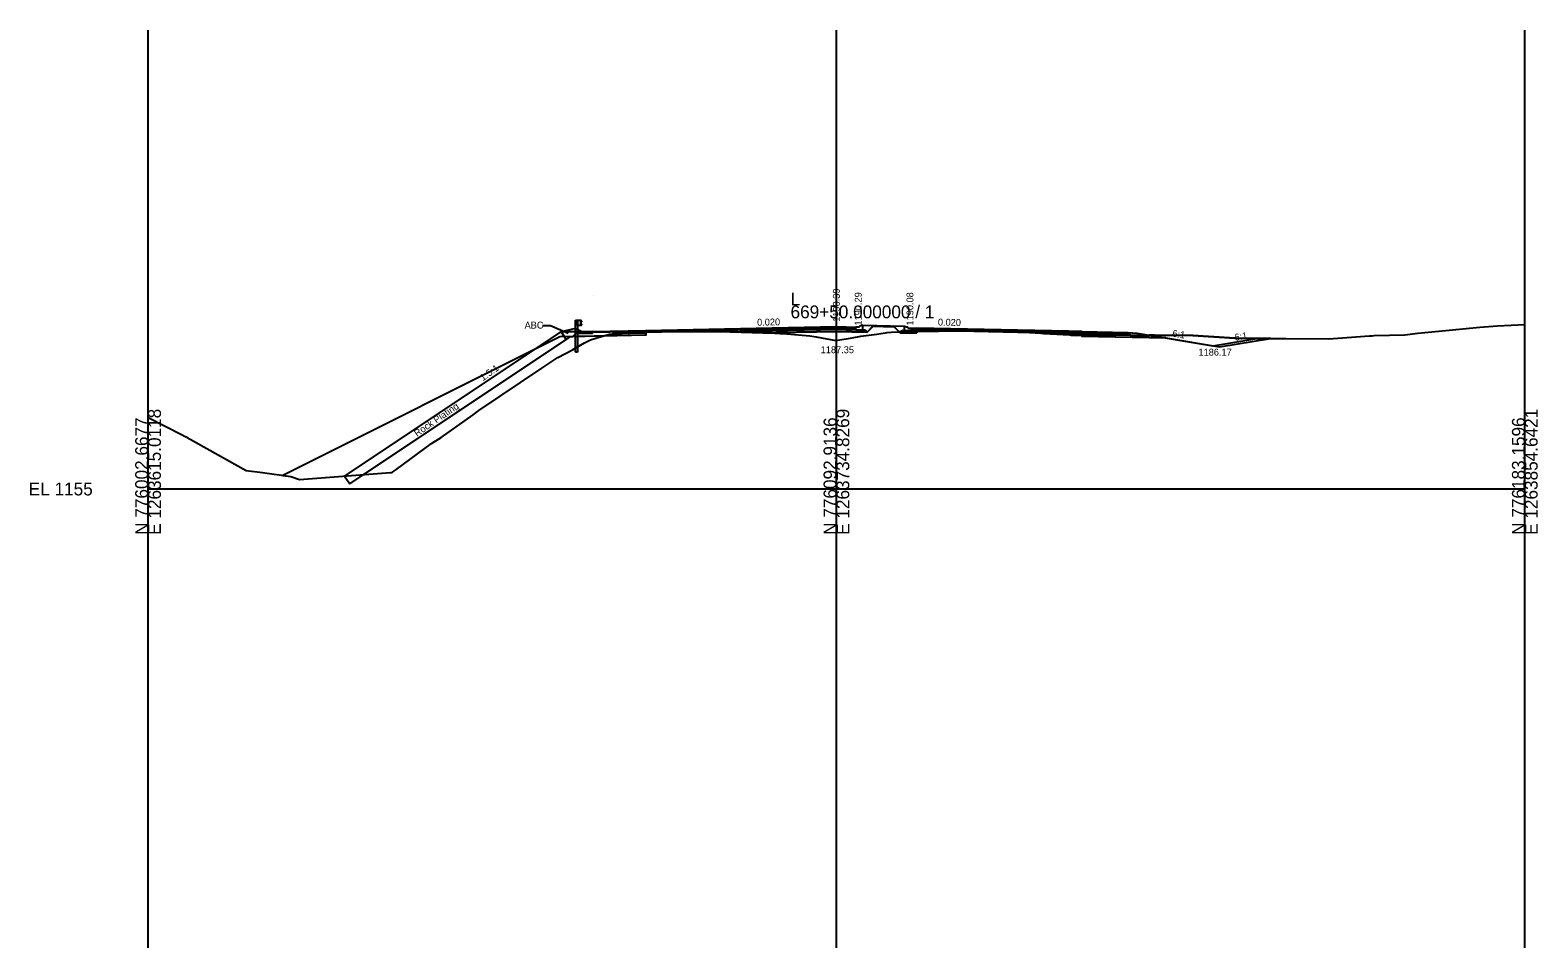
# Model space of a CAD drawing. Extents: x -41 to 1262860, y -100 to 777489.
# Drawn here: x -25.7 to 302.8, y 3130 to 3330 of the extents above; entities that cross this region are included whole.
import ezdxf

# ---------------------------------------------------------------- set-up
doc = ezdxf.new("R2010")
doc.units = 0
for name, color, linetype in [('Exist Cross Section Cell', 7, 'Continuous'), ('Exist XS Center Line Elevation Label', 7, 'Continuous'), ('Exist XS Ground Line', 7, 'Continuous'), ('Prop CMT Guardrail Graphics', 7, 'Continuous'), ('Prop CMT Pvmt Course 1', 7, 'Continuous'), ('Prop CMT Pvmt Course 2', 7, 'Continuous'), ('Prop CMT Pvmt Course 4', 7, 'Continuous'), ('Prop CMT Pvmt Surface', 7, 'Continuous'), ('Prop CMT Shld Paved Course 1', 7, 'Continuous'), ('Prop CMT Shld Paved Course 2', 7, 'Continuous'), ('Prop CMT Shld Paved Course 4', 7, 'Continuous'), ('Prop CMT Slope Grass', 7, 'Continuous'), ('Prop CMT Subgrade Earthwork', 7, 'Continuous'), ('Prop Conc Curb and Gutter', 7, 'Continuous'), ('Prop Conc Island Cover', 7, 'Continuous'), ('Prop XS Class II Rip Rap Ditch Liner', 7, 'Continuous'), ('Prop XS Ditch Standard Text', 7, 'Continuous'), ('Prop XS Earthwork Shape', 7, 'Continuous'), ('Prop XS Elevation Labels', 7, 'Continuous'), ('Prop XS Exc Vertical Line 1', 7, 'Continuous'), ('Prop XS Exc Vertical Line 2', 7, 'Continuous'), ('Prop XS Exc Vertical Line 3', 7, 'Continuous'), ('Prop XS Finish Grade', 7, 'Continuous'), ('Prop XS Hydro Elevations', 7, 'Continuous'), ('Prop XS SE Text', 7, 'Continuous'), ('Prop XS Side Slope Text', 7, 'Continuous'), ('Scratch_Level_0', 7, 'Continuous'), ('Scratch_Level_4', 7, 'Continuous'), ('Scratch_Level_5', 7, 'Continuous'), ('Scratch_Level_6', 7, 'Continuous'), ('Typical Curb CELL', 7, 'Continuous')]:
    doc.layers.add(name, color=color, linetype=linetype)

msp = doc.modelspace()

# ---------------------------------------------------------------- linework, layer by layer
at = {"layer": 'Exist Cross Section Cell'}
for p, q in [((150, 3230), (150, 3270)), ((0, 3230), (150, 3230)), ((150, 3230), (300, 3230))]:
    msp.add_line(p, q, dxfattribs=at)
at = {"layer": 'Exist XS Ground Line'}
msp.add_lwpolyline([(0, 3245.57), (7.42, 3241.82), (7.97, 3241.54), (8.29, 3241.35), (8.55, 3241.2), (21.4, 3234.01), (24.93, 3233.6), (31.13, 3232.71), (32.97, 3232.08), (52.85, 3233.58), (52.95, 3233.57), (53.09, 3233.61), (53.19, 3233.61), (53.34, 3233.71), (53.98, 3234.17), (61.78, 3239.91), (63.88, 3241.26), (70.84, 3246.15), (72.07, 3247.09), (85.84, 3256.37), (89.26, 3258.65), (92.52, 3260.3), (95.1, 3261.85), (96.38, 3262.52), (98.28, 3263.08), (100.55, 3263.76), (106.09, 3264.06), (107.94, 3264.15), (108.32, 3264.17), (111.86, 3264.28), (124.04, 3264.35), (124.13, 3264.35), (124.32, 3264.35), (136.54, 3263.94), (137.74, 3263.89), (139.19, 3263.82), (144.17, 3263.38), (145.58, 3263.17), (149.9, 3262.33), (153.44, 3262.98), (155.3, 3263.29), (158.77, 3263.76), (161.02, 3264.13), (161.89, 3264.17), (164.81, 3264.31), (167.6, 3264.34), (176.86, 3264.46), (179.93, 3264.39), (189.56, 3264.21), (192.06, 3264.08), (200.8, 3263.59), (201.1, 3263.56), (202.37, 3263.44), (203.52, 3263.49), (205.24, 3263.58), (214.29, 3263.54), (219.34, 3263.51), (227.67, 3263.44), (236.79, 3262.85), (240.26, 3262.81), (245.15, 3262.81), (246.28, 3262.83), (247.9, 3262.83), (257.29, 3262.72), (266.14, 3263.35), (266.72, 3263.39), (267.17, 3263.42), (273.85, 3263.61), (276.69, 3263.95), (281.26, 3264.41), (290.22, 3265.3), (294.07, 3265.58), (300, 3265.86)], dxfattribs=at)
at = {"layer": 'Prop CMT Guardrail Graphics'}
for p, q in [((93.11, 3266.79), (93.59, 3266.79)), ((93.11, 3264.29), (93.11, 3266.79)), ((93.59, 3265.61), (93.59, 3266.79)), ((93.59, 3266.79), (94.26, 3266.79)), ((93.59, 3266.79), (93.59, 3264.28)), ((94.26, 3266.79), (94.26, 3265.61)), ((94.26, 3266.71), (94.26, 3265.69)), ((94.36, 3266.69), (94.26, 3266.71)), ((94.26, 3265.69), (94.36, 3265.71)), ((94.27, 3266.24), (94.5, 3266.44)), ((94.27, 3266.15), (94.27, 3266.24)), ((94.5, 3265.95), (94.27, 3266.15)), ((94.5, 3266.59), (94.36, 3266.69)), ((94.36, 3265.71), (94.5, 3265.81)), ((94.5, 3266.44), (94.5, 3266.59)), ((94.5, 3265.81), (94.5, 3265.95)), ((93.11, 3259.79), (93.11, 3264.29)), ((94.26, 3265.61), (93.59, 3265.61)), ((93.59, 3264.28), (93.59, 3259.79)), ((93.59, 3259.79), (93.11, 3259.79))]:
    msp.add_line(p, q, dxfattribs=at)
at = {"layer": 'Prop CMT Pvmt Course 1'}
for p, q in [((94.5, 3264.28), (108.5, 3264.56)), ((132.5, 3265.04), (150, 3265.39)), ((132.5, 3264.79), (150, 3265.14)), ((150, 3265.39), (154.23, 3265.3)), ((150, 3265.14), (154.23, 3265.05)), ((154.23, 3265.3), (154.23, 3265.05)), ((166.33, 3265.06), (166.33, 3264.81)), ((166.33, 3265.06), (167.5, 3265.04)), ((203.5, 3264.32), (213.5, 3264.12))]:
    msp.add_line(p, q, dxfattribs=at)
for points in [[(108.5, 3264.31), (108.5, 3264.56), (108.5, 3264.56), (132.5, 3265.04), (132.5, 3264.79), (132.5, 3264.79), (108.5, 3264.31), (108.5, 3264.31), (108.5, 3264.31)], [(203.5, 3264.07), (203.5, 3264.32), (200.57, 3264.38), (200.57, 3264.38), (200.57, 3264.38), (167.5, 3265.04), (167.5, 3264.79), (167.5, 3264.79), (200.57, 3264.13), (200.57, 3264.13), (200.57, 3264.13), (203.5, 3264.07), (203.5, 3264.07)]]:
    msp.add_lwpolyline(points, dxfattribs=at)
at = {"layer": 'Prop CMT Pvmt Course 2'}
msp.add_lwpolyline([(166.33, 3264.48), (167.5, 3264.46), (167.5, 3264.46), (167.5, 3264.79), (166.33, 3264.81)], dxfattribs=at)
at = {"layer": 'Prop CMT Pvmt Course 4'}
for p, q in [((108.5, 3263.52), (93.44, 3263.22)), ((132.5, 3264.46), (132.5, 3264)), ((132.5, 3264), (150, 3264.35)), ((132.5, 3264), (150, 3264.35)), ((150, 3264.35), (156.69, 3264.21)), ((163.88, 3264.07), (167.5, 3264)), ((166.33, 3264.02), (166.33, 3264.48)), ((167.5, 3264.46), (167.5, 3264))]:
    msp.add_line(p, q, dxfattribs=at)
at = {"layer": 'Prop CMT Pvmt Surface'}
for p, q in [((96.85, 3264.33), (108.5, 3264.56)), ((108.5, 3264.56), (132.5, 3265.04)), ((132.5, 3265.04), (150, 3265.39)), ((150, 3265.39), (154.23, 3265.3)), ((166.33, 3265.06), (167.5, 3265.04)), ((167.5, 3265.04), (203.5, 3264.32)), ((203.5, 3264.32), (213.5, 3264.12))]:
    msp.add_line(p, q, dxfattribs=at)
at = {"layer": 'Prop CMT Shld Paved Course 1'}
for p, q in [((108.5, 3264.31), (96.85, 3264.08)), ((104.5, 3264.48), (104.5, 3264.48)), ((108.5, 3264.56), (108.5, 3264.31)), ((108.5, 3264.31), (108.5, 3264.31)), ((203.5, 3264.32), (203.5, 3264.07)), ((203.5, 3264.07), (203.5, 3264.07)), ((203.5, 3264.07), (213.76, 3263.86)), ((207.5, 3264.24), (207.5, 3264.24)), ((213.76, 3263.86), (213.5, 3264.12))]:
    msp.add_line(p, q, dxfattribs=at)
at = {"layer": 'Prop CMT Shld Paved Course 2'}
for p, q in [((97.1, 3272.23), (97.1, 3272.23)), ((97.1, 3272.23), (97.1, 3272.23)), ((97.1, 3272.23), (97.1, 3272.23)), ((97.1, 3272.23), (97.1, 3272.23)), ((97.1, 3272.23), (97.1, 3272.23)), ((97.1, 3272.23), (97.1, 3272.23)), ((108.5, 3263.98), (101.18, 3263.83)), ((103.9, 3263.88), (103.9, 3263.88)), ((103.9, 3263.88), (103.9, 3263.88)), ((111.86, 3264.38), (108.5, 3264.31)), ((108.5, 3264.31), (108.5, 3263.98)), ((108.5, 3264.31), (108.5, 3264.31)), ((108.5, 3264.31), (108.5, 3264.17)), ((108.5, 3264.17), (111.86, 3264.28)), ((108.5, 3264.17), (108.5, 3264.17)), ((108.5, 3264.17), (108.5, 3264.17)), ((108.5, 3263.98), (108.5, 3263.98)), ((124.04, 3264.62), (111.86, 3264.38)), ((111.86, 3264.38), (111.86, 3264.38)), ((111.86, 3264.38), (111.86, 3264.38)), ((111.86, 3264.28), (124.04, 3264.35)), ((111.86, 3264.28), (111.86, 3264.28)), ((111.86, 3264.28), (111.86, 3264.28)), ((124.13, 3264.62), (124.04, 3264.62)), ((124.04, 3264.62), (124.04, 3264.62)), ((124.04, 3264.35), (124.04, 3264.35)), ((124.04, 3264.35), (124.13, 3264.35)), ((124.32, 3264.63), (124.13, 3264.62)), ((124.13, 3264.35), (124.32, 3264.35)), ((132.5, 3264.79), (124.32, 3264.63)), ((124.32, 3264.63), (124.32, 3264.63)), ((124.32, 3264.35), (124.32, 3264.35)), ((124.32, 3264.35), (125.36, 3264.31)), ((125.36, 3264.31), (132.5, 3264.46)), ((125.36, 3264.31), (125.36, 3264.31)), ((132.5, 3264.46), (150, 3264.81)), ((132.5, 3264.46), (132.5, 3264.79)), ((132.5, 3264.79), (132.5, 3264.79)), ((132.5, 3264.46), (132.5, 3264.46)), ((132.5, 3264.46), (132.5, 3264.46)), ((150, 3264.81), (154.23, 3264.72)), ((154.23, 3264.72), (154.23, 3265.05)), ((166.33, 3264.48), (166.33, 3264.81)), ((203.5, 3264.07), (203.5, 3263.74)), ((203.5, 3263.74), (203.5, 3263.74)), ((203.5, 3263.74), (214.1, 3263.52)), ((214.1, 3263.52), (213.76, 3263.86))]:
    msp.add_line(p, q, dxfattribs=at)
msp.add_lwpolyline([(203.5, 3264.07), (203.5, 3264.07), (203.5, 3263.74), (203.5, 3263.74), (203.5, 3263.74), (203.5, 3263.74), (203.5, 3263.74), (202.37, 3263.76), (202.37, 3263.76), (202.37, 3263.76), (202.37, 3263.76), (201.1, 3263.78), (201.1, 3263.78), (200.8, 3263.79), (200.8, 3263.79), (200.57, 3263.79), (200.57, 3263.79), (195.2, 3263.9), (195.2, 3263.9), (192.06, 3264.08), (189.56, 3264.21), (189.56, 3264.21), (179.93, 3264.39), (179.93, 3264.39), (176.86, 3264.46), (176.86, 3264.46), (171.16, 3264.38), (171.16, 3264.38), (167.6, 3264.45), (167.6, 3264.45), (167.5, 3264.46), (167.5, 3264.46), (167.5, 3264.79), (167.6, 3264.79), (167.6, 3264.79), (176.86, 3264.6), (176.86, 3264.6), (179.93, 3264.54), (179.93, 3264.54), (189.56, 3264.35), (189.56, 3264.35), (192.06, 3264.3), (192.06, 3264.3), (200.57, 3264.13), (200.57, 3264.13), (200.8, 3264.12), (201.1, 3264.12), (201.1, 3264.12), (202.37, 3264.09), (202.37, 3264.09), (202.37, 3264.09), (202.37, 3264.09), (203.5, 3264.07), (203.5, 3264.07), (203.5, 3264.07)], dxfattribs=at)
at = {"layer": 'Prop CMT Shld Paved Course 4'}
for p, q in [((97.1, 3272.23), (97.1, 3272.23)), ((97.1, 3272.23), (97.1, 3272.23)), ((97.1, 3272.23), (97.1, 3272.23)), ((92.58, 3263.2), (93.32, 3263.94)), ((93.32, 3263.94), (93.83, 3263.94)), ((103.9, 3263.88), (103.9, 3263.88)), ((108.5, 3263.98), (108.5, 3263.52)), ((125.36, 3264.31), (132.5, 3264.08)), ((154.23, 3264.72), (156.23, 3264.68)), ((154.23, 3264.26), (156.69, 3264.21)), ((156.23, 3264.68), (156.69, 3264.21)), ((164.33, 3264.52), (163.88, 3264.07)), ((166.33, 3264.48), (164.33, 3264.52)), ((167.6, 3264.34), (167.5, 3264.34)), ((167.6, 3264.34), (171.16, 3264.38)), ((195.2, 3263.9), (200.8, 3263.59)), ((201.1, 3263.56), (200.8, 3263.59)), ((202.37, 3263.44), (201.1, 3263.56)), ((203.5, 3263.49), (202.37, 3263.44)), ((203.5, 3263.74), (203.5, 3263.28)), ((203.5, 3263.28), (214.56, 3263.06)), ((214.56, 3263.06), (214.1, 3263.52))]:
    msp.add_line(p, q, dxfattribs=at)
at = {"layer": 'Prop CMT Slope Grass'}
for q in [(90, 3264.26), (93.83, 3264.62)]:
    msp.add_line((93.14, 3264.97), q, dxfattribs=at)
at = {"layer": 'Prop CMT Subgrade Earthwork'}
for p, q in [((156.69, 3264.21), (158.12, 3265.64)), ((108.5, 3263.52), (91.99, 3263.19)), ((108.5, 3263.52), (108.5, 3264.17)), ((150, 3264.35), (132.5, 3264)), ((132.5, 3264), (132.5, 3264.08)), ((156.69, 3264.21), (150, 3264.35)), ((163.88, 3264.07), (162.39, 3265.56)), ((163.88, 3264.07), (167.5, 3264)), ((167.5, 3264), (167.5, 3264.34)), ((203.5, 3263.49), (203.5, 3263.28)), ((203.5, 3263.28), (221.78, 3262.91))]:
    msp.add_line(p, q, dxfattribs=at)
at = {"layer": 'Prop Conc Curb and Gutter'}
for p, q in [((155.73, 3265.69), (155.08, 3265.5)), ((155.73, 3264.69), (155.73, 3265.69)), ((154.91, 3265.29), (154.23, 3265.3)), ((154.23, 3264.72), (154.23, 3265.3)), ((154.23, 3264.72), (155.73, 3264.69)), ((154.98, 3265.37), (154.98, 3265.35)), ((164.83, 3265.51), (165.48, 3265.29)), ((164.83, 3264.51), (164.83, 3265.51)), ((166.33, 3264.48), (164.83, 3264.51)), ((165.58, 3265.15), (165.58, 3265.14)), ((165.64, 3265.08), (166.33, 3265.06)), ((166.33, 3264.48), (166.33, 3265.06))]:
    msp.add_line(p, q, dxfattribs=at)
for centre, radius, start, end in [((154.92, 3265.35), 0.0625, 268.8542, 357.7085), ((155.12, 3265.36), 0.146, 106.1434, 177.7085), ((165.43, 3265.15), 0.146, 0, 71.565), ((165.64, 3265.14), 0.0625, 180, 268.8542)]:
    msp.add_arc(centre, radius, start, end, dxfattribs=at)
at = {"layer": 'Prop Conc Island Cover'}
msp.add_line((155.73, 3265.69), (164.83, 3265.51), dxfattribs=at)
at = {"layer": 'Prop XS Class II Rip Rap Ditch Liner'}
for p, q in [((85.96, 3265.63), (87.66, 3265.63)), ((87.66, 3265.63), (91.54, 3263.93)), ((42.84, 3232.83), (90, 3264.27)), ((43.95, 3231.16), (91.99, 3263.19)), ((90, 3264.27), (91.11, 3262.6)), ((93.83, 3264.26), (90, 3264.26)), ((91.11, 3262.6), (91.99, 3263.19)), ((91.99, 3263.19), (92.58, 3263.2)), ((92.58, 3263.2), (93.32, 3263.94)), ((93.32, 3263.94), (93.83, 3263.94)), ((93.83, 3263.94), (93.83, 3264.26)), ((42.84, 3232.83), (43.95, 3231.16))]:
    msp.add_line(p, q, dxfattribs=at)
at = {"layer": 'Prop XS Earthwork Shape'}
for points in [[(31.13, 3232.71), (32.97, 3232.08), (52.85, 3233.58), (52.95, 3233.57), (53.09, 3233.61), (53.19, 3233.61), (53.34, 3233.71), (53.98, 3234.17), (61.78, 3239.91), (63.88, 3241.26), (70.84, 3246.15), (72.07, 3247.09), (85.84, 3256.37), (89.26, 3258.65), (92.52, 3260.3), (95.1, 3261.85), (96.38, 3262.52), (98.28, 3263.08), (99.13, 3263.33), (93.44, 3263.22), (89.7, 3263.14), (29.35, 3232.96)], [(99.13, 3263.33), (100.55, 3263.76), (106.09, 3264.06), (107.94, 3264.15), (108.32, 3264.17), (108.5, 3264.17), (108.5, 3263.52)], [(134.01, 3264.03), (132.5, 3264), (132.5, 3264.08)], [(156.69, 3264.21), (150, 3264.35), (134.01, 3264.03), (136.54, 3263.94), (137.74, 3263.89), (139.19, 3263.82), (144.17, 3263.38), (145.58, 3263.17), (149.9, 3262.33), (153.44, 3262.98), (155.3, 3263.29), (158.77, 3263.76), (161.02, 3264.13), (161.89, 3264.17), (163.7, 3264.26), (162.65, 3265.3), (157.87, 3265.39)], [(167.5, 3264), (167.5, 3264.34), (164.81, 3264.31), (163.7, 3264.26), (163.88, 3264.07)], [(203.5, 3263.49), (203.5, 3263.28), (214.56, 3263.06), (214.07, 3263.54), (205.24, 3263.58), (203.52, 3263.49)], [(218.14, 3263.52), (221.78, 3262.91), (214.56, 3263.06), (214.07, 3263.54), (214.29, 3263.54)], [(221.78, 3262.91), (233.5, 3260.96), (244.62, 3262.81), (240.26, 3262.81), (236.79, 3262.85), (227.67, 3263.44), (219.34, 3263.51), (218.14, 3263.52)]]:
    msp.add_lwpolyline(points, close=True, dxfattribs=at)
at = {"layer": 'Prop XS Exc Vertical Line 1'}
msp.add_line((0, 3130), (0, 3330), dxfattribs=at)
at = {"layer": 'Prop XS Exc Vertical Line 2'}
msp.add_line((150, 3130), (150, 3330), dxfattribs=at)
at = {"layer": 'Prop XS Exc Vertical Line 3'}
msp.add_line((300, 3130), (300, 3330), dxfattribs=at)
at = {"layer": 'Prop XS Finish Grade'}
for p, q in [((91.11, 3262.6), (46.91, 3233.13)), ((213.5, 3264.12), (215.5, 3263.96)), ((213.5, 3264.12), (214.56, 3263.06)), ((215.5, 3263.96), (232, 3261.21)), ((232, 3261.21), (241.62, 3262.81))]:
    msp.add_line(p, q, dxfattribs=at)
at = {"layer": 'Scratch_Level_0'}
for p, q in [((155.73, 3265.69), (155.73, 3265.44)), ((164.83, 3265.51), (164.83, 3265.26))]:
    msp.add_line(p, q, dxfattribs=at)
at = {"layer": 'Scratch_Level_4'}
msp.add_line((300, 3130), (300, 3330), dxfattribs=at)
at = {"layer": 'Scratch_Level_5'}
msp.add_line((150, 3251.71), (150, 3283.6), dxfattribs=at)
at = {"layer": 'Scratch_Level_6'}
msp.add_line((0, 3130), (0, 3330), dxfattribs=at)
at = {"layer": 'Typical Curb CELL'}
for p, q in [((93.83, 3263.94), (93.83, 3264.62)), ((94.52, 3264.27), (93.83, 3264.62)), ((93.83, 3263.94), (96.85, 3263.91)), ((93.87, 3264.24), (94.02, 3264.28)), ((94, 3264.19), (93.87, 3264.24)), ((94.02, 3264.28), (94, 3264.19)), ((94.54, 3264.15), (94.43, 3264.07)), ((94.43, 3264.07), (94.6, 3264.03)), ((96.84, 3264.33), (94.52, 3264.27)), ((94.6, 3264.03), (94.54, 3264.15)), ((95.28, 3264.2), (95.24, 3264.08)), ((95.24, 3264.08), (95.36, 3264.08)), ((95.36, 3264.08), (95.28, 3264.2)), ((95.78, 3264.14), (95.68, 3264.06)), ((95.68, 3264.06), (95.85, 3264.02)), ((95.85, 3264.02), (95.78, 3264.14)), ((96.53, 3264.18), (96.49, 3264.07)), ((96.49, 3264.07), (96.61, 3264.06)), ((96.61, 3264.06), (96.53, 3264.18)), ((96.85, 3264.33), (96.85, 3264.33)), ((96.85, 3263.91), (96.85, 3264.32))]:
    msp.add_line(p, q, dxfattribs=at)
for centre in [(93.9, 3264.32), (93.99, 3264.05), (94.11, 3264.1), (94.37, 3264.12), (94.38, 3264.07), (94.56, 3263.99), (94.59, 3264.09), (94.78, 3264.05), (94.83, 3264.16), (94.96, 3264.13), (94.99, 3264), (95.05, 3264.04), (95.24, 3264.04), (95.36, 3264.09), (95.45, 3264.08), (95.55, 3264.03), (95.61, 3264.17), (95.62, 3264.11), (95.63, 3264.06), (95.84, 3264.08), (96.03, 3264.03), (96.08, 3264.15), (96.13, 3264.12), (96.21, 3264.12), (96.24, 3263.99), (96.29, 3264.03), (96.36, 3264.2), (96.72, 3264.27), (96.76, 3264.15)]:
    msp.add_circle(centre, 0.00802, dxfattribs=at)
msp.add_arc((96.84, 3264.32), 0.0104, 359.4338, 91.4818, dxfattribs=at)

# ---------------------------------------------------------------- texts
at = {"layer": 'Exist Cross Section Cell'}
for s, p in [('L', (140, 3270)), ('669+50.000000 / 1', (140, 3267.2)), ('EL 1155', (-26, 3228.6))]:
    msp.add_text(s, height=2.8, dxfattribs=at).set_placement(p)
for s, p in [('E 1263615.0118', (2.8, 3220)), ('E 1263734.8269', (152.8, 3220)), ('E 1263854.6421', (302.8, 3220)), ('N 776002.6677', (0, 3220)), ('N 776092.9136', (150, 3220)), ('N 776183.1596', (300, 3220))]:
    msp.add_text(s, height=2.8, rotation=90, dxfattribs=at).set_placement(p)
at = {"layer": 'Exist XS Center Line Elevation Label'}
msp.add_text('1187.35', height=1.5, dxfattribs=at).set_placement((146.57, 3259.6))
at = {"layer": 'Prop XS Ditch Standard Text'}
msp.add_text('1186.17', height=1.5, dxfattribs=at).set_placement((228.89, 3259.07))
at = {"layer": 'Prop XS Elevation Labels'}
for s, p in [('1190.29', (155.49, 3265.63)), ('1190.08', (166.77, 3265.63))]:
    msp.add_text(s, height=1.5, rotation=90, dxfattribs=at).set_placement(p)
at = {"layer": 'Prop XS Hydro Elevations'}
msp.add_text('1190.39', height=1.5, rotation=90, dxfattribs=at).set_placement((150.73, 3266.44))
at = {"layer": 'Prop XS SE Text'}
for rotation, p in [(1.1458, (132.72, 3265.58)), (358.8542, (172.1, 3265.63))]:
    msp.add_text('0.020', height=1.5, rotation=rotation, dxfattribs=at).set_placement(p)
at = {"layer": 'Prop XS Side Slope Text'}
for s, rotation, p in [('ABC', 0.2627, (82.05, 3264.95)), ('6:1', 350.5377, (223.09, 3263.23)), ('6:1', 9.4809, (236.87, 3262.28)), ('1.5:1', 35.2045, (72.96, 3253.45)), ('Rock Plating', 34.4049, (58.6, 3241.34))]:
    msp.add_text(s, height=1.5, rotation=rotation, dxfattribs=at).set_placement(p)

doc.saveas('drawing.dxf')
